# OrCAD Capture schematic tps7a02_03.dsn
size A
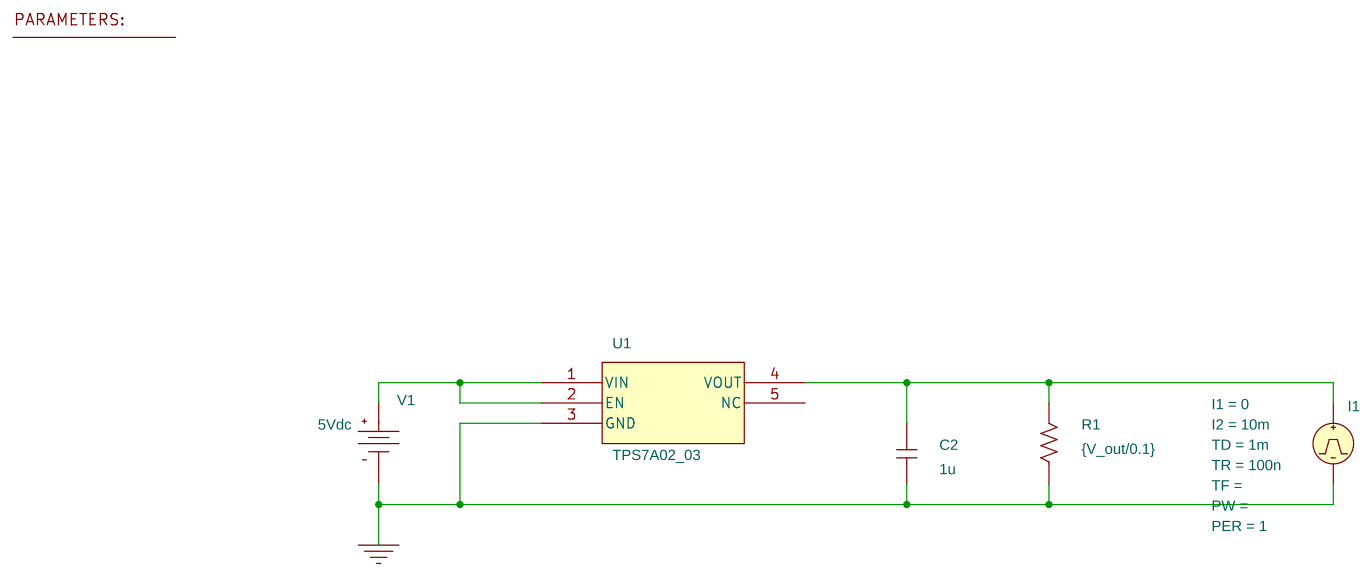
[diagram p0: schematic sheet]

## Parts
1  PARAM
C2  1u  [cap196]
I1  IPULSE
R1  {V_out/0.1}  [AXRC05]
U1  TPS7A02_03
V1  VDC

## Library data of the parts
1 = PARAM: V_out: 1.8
C2 = C
I1 = IPULSE: I1: 0; I2: 10m; PER: 1; TD: 1m; TR: 100n
R1 = R
U1 = TPS7A0X: PSpiceTemplate: X^@REFDES %VIN %EN %GND %VOUT %NC @MODEL
V1 = VDC: DC: 5Vdc

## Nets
0: C2.1 I1.2(-) R1.1 U1.3(GND) V1.1(-)
N02186: U1.1(VIN) U1.2(EN) V1.0(+)
N02204: C2.2 I1.1(+) R1.2 U1.4(VOUT)

Not connected (* = marked no-connect by the designer): U1 5(NC)
